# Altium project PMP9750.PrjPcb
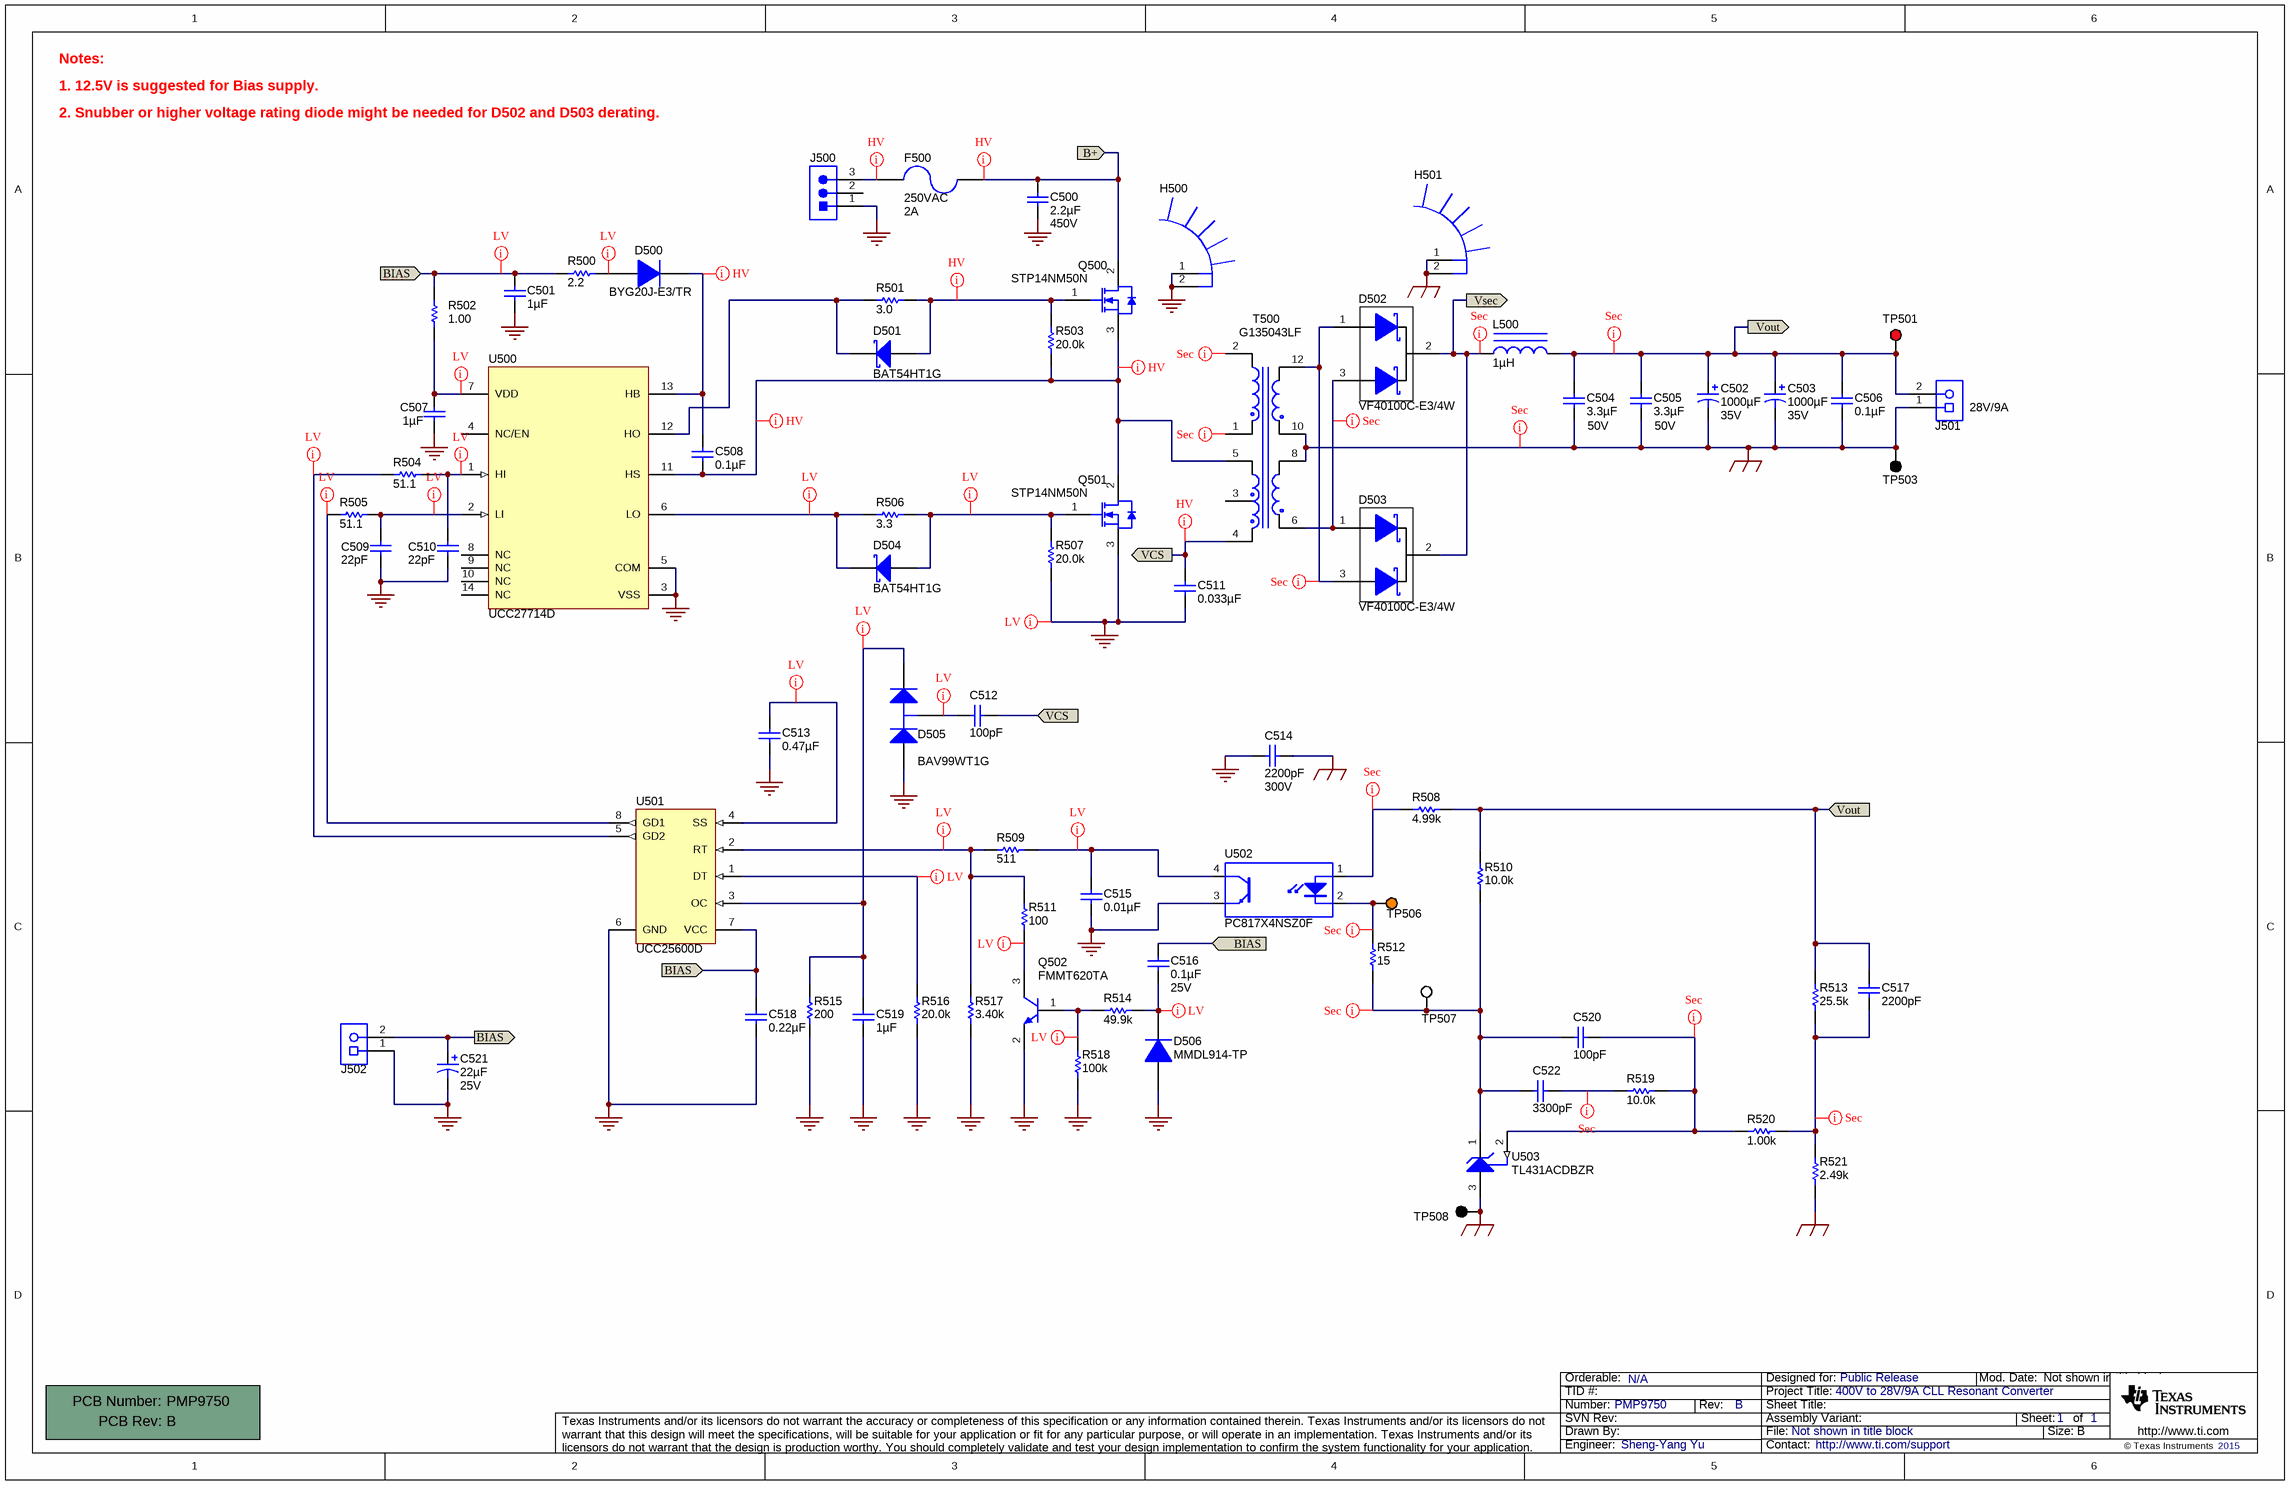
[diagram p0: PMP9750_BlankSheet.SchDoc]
TechSupport: http://www.ti.com/support; SCH_Rev: B; PRJ_Title: 400V to 28V/9A CLL Resonant Converter; PRJ_Number: PMP9750; PRJ_Engineer: Sheng-Yang Yu; PRJ_Customer: Public Release; PCB_Rev: B; PCB_Layout: Sheng-Yang Yu; EVM_Orderable: N/A; CopyrightYear: 2015
1 sheet, 73 parts. Net scope: flat (ports and power ports of the same name join across sheets).
Board file: PMP9750_TID.PcbDoc

## Sheet PMP9750_BlankSheet.SchDoc
size 431 x 279 mm; Date: Not shown in title block; ApprovedBy: Not shown in title block; CheckedBy: Not shown in title block; Author: Not shown in title block; CompanyName: Not shown in title block; Engineer: Not shown in title block; Organization: Not shown in title block; Address1: Not shown in title block; Address2: Not shown in title block; Address3: Not shown in title block; Address4: Not shown in title block; DocumentNumber: 1; Revision: Use project parameter SCH_Rev; SheetNumber: 1; SheetTotal: 1; PageSetup: Record=PageOptions¦CenterHorizontal=True¦CenterVertical=True¦PrintScale=1.00¦XCorrection=1.00¦YCorrection=1.00¦PrintKind=0¦BorderSize=5000000¦LeftOffset=0¦BottomOffset=0¦Orientation=2¦PaperLength=1000¦PaperWidth=1000¦Scale=100¦PaperSource=15¦PrintQuality=600¦MediaType=1¦DitherType=10¦PaperKind=Letter¦PrintScaleMode=1

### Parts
!PCB500  Printed Circuit Board  (value not drawn)  (mechanical)
C500  ValueDisplayed: 2.2µF  Value2: 450V  [MPK_1800x2000x1350]  (hidden comment: 450MPK225J)
C501  ValueDisplayed: 1µF  [0603]  (hidden comment: UMK107AB7105KA-T)
C502  ValueDisplayed: 1000µF  Value2: 35V  [CAPPR5-10X20]  (hidden comment: 35ZLH1000MEFC12.5X20)
C503  ValueDisplayed: 1000µF  Value2: 35V  [CAPPR5-10X20]  (hidden comment: 35ZLH1000MEFC12.5X20)
C504  ValueDisplayed: 3.3µF  Value2: 50V  [1210]  (hidden comment: C3225X7R1H335M)
C505  ValueDisplayed: 3.3µF  Value2: 50V  [1210]  (hidden comment: C3225X7R1H335M)
C506  ValueDisplayed: 0.1µF  [0805_HV]  (hidden comment: 08055C104KAT2A)
C507  ValueDisplayed: 1µF  [0805_HV]  (hidden comment: GMK212B7105KG-T)
C508  ValueDisplayed: 0.1µF  [1206]  (hidden comment: 12065C104KAT2A)
C509  ValueDisplayed: 22pF  [0603]  (hidden comment: C0603C220J5GACTU)
C510  ValueDisplayed: 22pF  [0603]  (hidden comment: C0603C220J5GACTU)
C511  ValueDisplayed: 0.033µF  [CAPRR1500W80L1800T950H1800]  (hidden comment: 121MPE333J)
C512  ValueDisplayed: 100pF  [1808]  (hidden comment: VJ1808Y101KXEAT5Z)
C513  ValueDisplayed: 0.47µF  [0603]  (hidden comment: C0603C474K4RACTU)
C514  ValueDisplayed: 2200pF  Value2: 300V  [E_900x700x900]  (hidden comment: DE6E3KJ222MN3A)
C515  ValueDisplayed: 0.01µF  [0603]  (hidden comment: C0603C103K5RACTU)
C516  ValueDisplayed: 0.1µF  Value2: 25V  [0603]  (hidden comment: 06033C104JAT2A)
C517  ValueDisplayed: 2200pF  [0603]  (hidden comment: C0603C222K5RAC)
C518  ValueDisplayed: 0.22µF  [0805_HV]  (hidden comment: 08053C224JAT2A)
C519  ValueDisplayed: 1µF  [0603]  (hidden comment: C0603C105K4PACTU)
C520  ValueDisplayed: 100pF  [0603]  (hidden comment: C1608C0G1H101J)
C521  ValueDisplayed: 22µF  Value2: 25V  [ML_500x500]  (hidden comment: 25ML22MEFC5X5)
C522  ValueDisplayed: 3300pF  [0603]  (hidden comment: 06031C332KAT2A)
D500  BYG20J-E3/TR  [SMA]
D501  BAT54HT1G  [sod-323]
D502  VF40100C-E3/4W  [TO-220AB]
D503  VF40100C-E3/4W  [TO-220AB]
D504  BAT54HT1G  [sod-323]
D505  BAV99WT1G  [SOT-323]
D506  MMDL914-TP  [sod-323]
F500  VAC_V: 250VAC  Irating_A: 2A  [FUSE_372]  (hidden comment: 37212000001)
H500  578622B03200G  [HSINK_578622B03200G]  (value not drawn)
H501  513002B02500G  [HSINK_513201B02500]  (value not drawn)
J500  1715734  [Phoenix_1715734]  (value not drawn)
J501  1715721  [PhoenixContact_1715721]  (value not drawn)
J502  1715721  [PhoenixContact_1715721]  (value not drawn)
L500  ValueDisplayed: 1µH  [WE-HCC_1210]  (hidden comment: 7443320100)
Q500  STP14NM50N  [TO-220AB_100mil]
Q501  STP14NM50N  [TO-220AB_100mil]
Q502  FMMT620TA  [SOT-23]
R500  ValueDisplayed: 2.2  [0805_HV]  (hidden comment: CRCW08052R20JNEA)
R501  value 3.0  [0603]  (hidden comment: CRCW06033R00JNEA)
R502  value 1.00  [0805_HV]  (hidden comment: ERJ-6RQF1R0V)
R503  value 20.0k  [0805_HV]  (hidden comment: CRCW080520K0FKEA)
R504  ValueDisplayed: 51.1  [0603]  (hidden comment: CRCW060351R1FKEA)
R505  ValueDisplayed: 51.1  [0603]  (hidden comment: CRCW060351R1FKEA)
R506  ValueDisplayed: 3.3  [1206]  (hidden comment: CRCW12063R30JNEA)
R507  value 20.0k  [0805_HV]  (hidden comment: CRCW080520K0FKEA)
R508  value 4.99k  [0805_HV]  (hidden comment: CRCW08054K99FKEA)
R509  ValueDisplayed: 511  [0603]  (hidden comment: CRCW0603511RFKEA)
R510  value 10.0k  [0603]  (hidden comment: CRCW060310K0FKEA)
R511  ValueDisplayed: 100  [0603]  (hidden comment: CRCW0603100RFKEA)
R512  value 15  [0603]  (hidden comment: CRCW060315R0JNEA)
R513  value 25.5k  [0603]  (hidden comment: CRCW060325K5FKEA)
R514  ValueDisplayed: 49.9k  [0603]  (hidden comment: CRCW060349K9FKEA)
R515  value 200  [0603]  (hidden comment: CRCW0603200RFKEA)
R516  value 20.0k  [0603]  (hidden comment: CRCW060320K0FKEA)
R517  value 3.40k  [0603]  (hidden comment: CRCW06033K40FKEA)
R518  ValueDisplayed: 100k  [0603]  (hidden comment: CRCW0603100KFKEA)
R519  value 10.0k  [0603]  (hidden comment: CRCW060310K0FKEA)
R520  value 1.00k  [0603]  (hidden comment: CRCW06031K00FKEA)
R521  value 2.49k  [0603]  (hidden comment: CRCW06032K49FKEA)
T500  G135043LF  [XFMR_GCI-1240x965x1213]
TP501  5000  [Keystone5000]  (value not drawn)
TP503  5001  [Keystone5001]  (value not drawn)
TP506  5003  [Keystone5003]  (value not drawn)
TP507  5002  [Keystone5002]  (value not drawn)
TP508  5001  [Keystone5001]  (value not drawn)
U500  UCC27714D  [D0014A_N]
U501  UCC25600D  [D0008A_N]
U502  PC817X4NSZ0F  [DIP762W60P254L460H350Q4B]
U503  TL431ACDBZR  [DBZ0003A_N]

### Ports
B+ (in), BIAS (in), BIAS (out), VCS (in), VCS (out), Vout (in), Vout (out), Vsec (out)

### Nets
GND: C500.2 C501.1 C507.1 C509.2 C510.2 C511.2 C513.2 C514.2 C515.2 C518.2 C519.2 C521.2(-) D505.1(A) D506.2(A) H500.1 H500.2 J500.1 J502.1 Q501.3(S) Q502.2(E) R507.2 R515.1 R516.1 R517.1 R518.2 U500.3(VSS) U500.5(COM) U501.6(GND) U502.3(E)
GND2: C502.2(-) C503.2(-) C504.2 C505.2 C506.2 C514.1 H501.1 H501.2 J501.1 R521.1 T500.8 T500.10 TP503.1 TP508.1 U503.3(ANODE)
B+: C500.1 F500.1 Q500.2(D) ; port B+
BIAS: C501.2 C516.1 C518.1 C521.1(+) J502.2 R500.1 R502.2 U501.7(VCC) ; port BIAS
VCS: C511.1 C512.1 T500.4 ; port VCS
Vout: C502.1(+) C503.1(+) C504.1 C505.1 C506.1 C517.1 J501.2 L500.2 R508.2 R510.2 R513.2 TP501.1 ; port Vout
Vsec: D502.2(K) D503.2(K) L500.1 ; port Vsec
NetC507_2: C507.2 R502.1 U500.7(VDD)
NetC508_1: C508.1 D500.1(K) U500.13(HB)
NetC508_2: C508.2 Q500.3(S) Q501.2(D) R503.2 T500.5 U500.11(HS)
NetC509_1: C509.1 R505.2 U500.2(LI)
NetC510_1: C510.1 R504.2 U500.1(HI)
NetC512_2: C512.2 D505.3(C)
NetC513_1: C513.1 U501.4(SS)
NetC515_1: C515.1 R509.2 U502.4(C)
NetC516_2: C516.2 D506.1(K) R514.1
NetC517_2: C517.2 R513.1 R520.2 R521.2
NetC519_1: C519.1 D505.2(K) R515.2 U501.3(OC)
NetC520_1: C520.1 R519.2 R520.1 U503.2(REF)
NetC520_2: C520.2 C522.2 R510.1 R512.2 TP507.1 U503.1(CATHODE)
NetC522_1: C522.1 R519.1
NetD500_2: D500.2(A) R500.2
NetD501_1: D501.1(K) R501.1 U500.12(HO)
NetD501_2: D501.2(A) Q500.1(G) R501.2 R503.1
NetD502_1: D502.1(A) D503.3(A) T500.12
NetD502_3: D502.3(A) D503.1(A) T500.6
NetD504_1: D504.1(K) R506.1 U500.6(LO)
NetD504_2: D504.2(A) Q501.1(G) R506.2 R507.1
NetF500_2: F500.2 J500.3
NetQ502_1: Q502.1(B) R514.2 R518.1
NetQ502_3: Q502.3(C) R511.1
NetR504_1: R504.1 U501.5(GD2)
NetR505_1: R505.1 U501.8(GD1)
NetR508_1: R508.1 U502.1(A)
NetR509_1: R509.1 R511.2 R517.2 U501.2(RT)
NetR512_1: R512.1 TP506.1 U502.2(K)
NetR516_2: R516.2 U501.1(DT)

Not connected (* = marked no-connect by the designer): J500 2; T500 1 2 3; U500 4(NC/EN) 8(NC) 9(NC) 10(NC) 14(NC)

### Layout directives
net class HV_pri: B+, NetC508_1, NetC508_2, NetD501_2, NetF500_2, VCS
net class Sec: GND2, NetC517_2, NetC520_1, NetC520_2, NetC522_1, NetD502_1, NetD502_3, NetR508_1, NetR512_1, NetT500_1, NetT500_2, Vout, Vsec
net class LV_pri: BIAS, GND, NetC507_2, NetC509_1, NetC510_1, NetC512_2, NetC513_1, NetC515_1, NetC516_2, NetC519_1, NetD500_2, NetD504_1, NetD504_2, NetQ502_1, NetQ502_3, NetR504_1, NetR505_1, NetR509_1, NetR516_2

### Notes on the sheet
- Notes:
- 1. 12.5V is suggested for Bias supply.
- 2. Snubber or higher voltage rating diode might be needed for D502 and D503 derating.
- (near J501) 28V/9A

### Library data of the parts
!PCB500 = PCB: Manufacturer: Any; PartNumber: PMP9750; SymbolCreator: a0412235
C500 = 450MPK225J: CAP, Film, 2.2 µF, 450 V, +/- 5%, TH; Manufacturer: Rubycon; Polarized: N; CompType: Capacitor; Value: 2.2uF; U/M: EA; Cap_F: 0.0000022; Tolerance_%: 5; Value1: Unknown; VDC_V: 450; TaMin_C: -40; TaMax_C: 105
C501 = UMK107AB7105KA-T: CAP, CERM, 1 µF, 50 V, +/- 10%, X7R, 0603; Manufacturer: Taiyo Yuden; Polarized: N; CompType: Capacitor; Value: 1uF; U/M: EA; Cap_F: 0.000001; Tolerance_%: 10; Value1: Unknown; VDC_V: 50; Value2: 50V; TaMin_C: -55; TaMax_C: 125
C502 C503 = EEU-FR1V681: CAP, AL, 680uF, 35V, +/-20%, TH; Manufacturer: Rubycon; Polarized: Y; CompType: Capacitor; Value: 1000uF; U/M: EA; Tolerance_%: 20; Value1: Unknown; VDC_V: 35; IRMS_A: 2.47; TaMin_C: -40; TaMax_C: 105
C504 C505 = C3225X7R1H335M: CAP, CERM, 3.3uF, 50V, +/-20%, X7R, 1210; Manufacturer: TDK; Polarized: N; CompType: Capacitor; U/M: EA; Cap_F: 0.0000033; Tolerance_%: 20; Value1: Unknown; VDC_V: 50; TaMin_C: -55; TaMax_C: 125
C506 = 08055C104KAT2A: CAP, CERM, 0.1uF, 50V, +/-10%, X7R, 0805; Manufacturer: AVX; Polarized: N; CompType: Capacitor; U/M: EA; Cap_F: 0.0000001; Tolerance_%: 10; ESR_Ohm: 0.024; Value1: 0.024 ohm; VDC_V: 50; TaMin_C: -55; TaMax_C: 125; Cap_Case: 0805
C507 = GMK212B7105KG-T: CAP, CERM, 1uF, 35V, +/-10%, X7R, 0805; Manufacturer: Taiyo Yuden; Polarized: N; CompType: Capacitor; U/M: EA; Cap_F: 0.000001; Tolerance_%: 10; Value1: Unknown; VDC_V: 35; TaMin_C: -55; TaMax_C: 125; Cap_Case: 0805
C508 = 12065C104KAT2A: CAP, CERM, 0.1 µF, 50 V, +/- 10%, X7R, 1206; Manufacturer: AVX; Polarized: N; CompType: Capacitor; Value: 0.1uF; U/M: EA; Cap_F: 0.0000001; Tolerance_%: 10; ESR_ohm: 0.037; Value1: 0.037 ohm; VDC_V: 50; Value2: 50V; TaMin_C: -55; TaMax_C: 125
C509 C510 = C0603C220J5GACTU: CAP, CERM, 22 pF, 50 V, +/- 5%, C0G/NP0, 0603; Manufacturer: Kemet; Polarized: N; CompType: Capacitor; Value: 22pF; U/M: EA; Cap_F: 0.000000000022; Tolerance_%: 5; Value1: Unknown; VDC_V: 50; Value2: 50V; TaMin_C: -55; TaMax_C: 125
C511 = 121MPE333J: CAP, Film, 0.033uF, 1250V, +/-5%, TH; Manufacturer: Rubycon; Polarized: N; CompType: Capacitor; U/M: EA; Cap_F: 0.000000033; Tolerance_%: 5; Value1: Unknown; VDC_V: 1250; TaMin_C: -40; TaMax_C: 105; Cap_Case: 18x9.5x18mm
C512 = VJ1808Y101KXEAT5Z: CAP, CERM, 100pF, 500V, +/-10%, X7R, 1808; Manufacturer: Vishay-Vitramon; Polarized: N; CompType: Capacitor; U/M: EA; Cap_F: 0.0000000001; Tolerance_%: 10; Value1: Unknown; VDC_V: 500; TaMin_C: -55; TaMax_C: 125
C513 = C0603C474K4RACTU: CAP, CERM, 0.47uF, 16V, +/-10%, X7R, 0603; Manufacturer: Kemet; Polarized: N; CompType: Capacitor; U/M: EA; Cap_F: 0.00000047; Tolerance_%: 10; Value1: Unknown; VDC_V: 16; TaMin_C: -55; TaMax_C: 125
C514 = DE6E3KJ222MN3A: CAP, CERM, 2200 pF, 300 V, +/- 20%, E, TH, 2- Leads, Body 9x7mm, Pin Spacing 7.5mm; Manufacturer: MuRata; Polarized: N; CompType: Capacitor; Value: 2200pF; U/M: EA; Cap_F: 0.0000000022; Tolerance_%: 20; Value1: Unknown; VDC_V: 300; TaMin_C: -40; TaMax_C: 125; Cap_Case: 9x7x9mm
C515 = C0603C103K5RACTU: CAP, CERM, 0.01uF, 50V, +/-10%, X7R, 0603; Manufacturer: Kemet; Polarized: N; CompType: Capacitor; U/M: EA; Cap_F: 0.00000001; Tolerance_%: 10; Value1: Unknown; VDC_V: 50; TaMin_C: -55; TaMax_C: 125
C516 = 06033C104JAT2A: CAP, CERM, 0.1 µF, 25 V, +/- 5%, X7R, 0603; Manufacturer: AVX; Polarized: N; CompType: Capacitor; Value: 0.1uF; U/M: EA; Cap_F: 0.0000001; Tolerance_%: 5; ESR_ohm: 0.05; Value1: 0.05 ohm; VDC_V: 25; TaMin_C: -55; TaMax_C: 125
C517 = C0603C222K5RAC: CAP, CERM, 2200pF, 50V, +/-10%, X7R, 0603; Manufacturer: Kemet; Polarized: N; CompType: Capacitor; U/M: EA; Cap_F: 0.0000000022; Tolerance_%: 10; Value1: Unknown; VDC_V: 50; TaMin_C: -55; TaMax_C: 125
C518 = 08053C224JAT2A: CAP, CERM, 0.22uF, 25V, +/-5%, X7R, 0805; Manufacturer: AVX; Polarized: N; CompType: Capacitor; U/M: EA; Cap_F: 0.00000022; Tolerance_%: 5; ESR_Ohm: 0.016; Value1: 0.016 ohm; VDC_V: 25; TaMin_C: -55; TaMax_C: 125; Cap_Case: 0805
C519 = C0603C105K4PACTU: CAP, CERM, 1uF, 16V, +/-10%, X5R, 0603; Manufacturer: Kemet; Polarized: N; CompType: Capacitor; U/M: EA; Cap_F: 0.000001; Tolerance_%: 10; Value1: Unknown; VDC_V: 16; TaMin_C: -55; TaMax_C: 85
C520 = C1608C0G1H101J: CAP, CERM, 100pF, 50V, +/-5%, C0G/NP0, 0603; Manufacturer: TDK; Polarized: N; CompType: Capacitor; U/M: EA; Cap_F: 0.0000000001; Tolerance_%: 5; ESR_Ohm: 0.1679; Value1: 0.1679 ohm; VDC_V: 50; TaMin_C: -55; TaMax_C: 125
C521 = 25ML22MEFC5X5: CAP, AL, 22 µF, 25 V, +/- 20%, TH; Manufacturer: Rubycon; Polarized: Y; CompType: Capacitor; Value: 22uF; U/M: EA; Cap_F: 0.000022; Tolerance_%: 20; Value1: Unknown; VDC_V: 25; IRMS_A: 0.042; TaMin_C: -40; TaMax_C: 105; Cap_Case: 5x5
C522 = 06031C332KAT2A: CAP, CERM, 3300pF, 100V, +/-10%, X7R, 0603; Manufacturer: AVX; Polarized: N; CompType: Capacitor; U/M: EA; Cap_F: 0.0000000033; Tolerance_%: 10; ESR_Ohm: 0.159; Value1: 0.159 ohm; VDC_V: 100; TaMin_C: -55; TaMax_C: 125
D500 = BYG20J-E3/TR: Diode, Ultrafast, 600V, 1.5A, SMA; Manufacturer: Vishay-Semiconductor; U/M: EA; Vf_V: 1.4; Value2: 1.4V; Io_A: 1.5; Vr_V: 600; TJmax_C: 150
D501 D504 = BAT54HT1G: Diode, Schottky, 30V, 0.2A, SOD-323; Manufacturer: ON Semiconductor; Value: 0.35V; U/M: EA; Vf_V: 0.35; Io_A: 0.2; Vr_V: 30
D502 D503 = VF40100C-E3/4W: Diode, Schottky, 100 V, 20 A, TH; Manufacturer: Vishay-Semiconductor; SymbolCreator: a0411947; U/M: EA; Vf_V: 0.73; Value: 100V; Value1: 20A; Value2: 0.73V; Io_A: 20; Vr_V: 100; TJmax_C: 150; RJC_CperW: 2
D505 = BAV99WT1G: Diode, P-N, 70V, 0.2A, SOT-323; Manufacturer: Fairchild Semiconductor; Value: 0.63V; U/M: EA; Vf_V: 0.63; Io_A: 0.2; Vr_V: 70; TJmax_C: 150
D506 = MMDL914-TP: Diode, Switching, 100 V, 0.2 A, SOD-323; Manufacturer: Micro Commercial Components; U/M: EA; Vf_V: 1; Value: 100V; Value1: 0.2A; Value2: 1V; Io_A: 0.2; Vr_V: 100; TJmax_C: 150; RJC_CperW: 635
F500 = 37212000001: Fuse, 2 A, 250 V, TH; Manufacturer: Littelfuse; U/M: EA; OpeningTime_200%_max: 2; VDC_V: 250; Vdrop: 0.085; Soldering_Wave_MaxTemp_C: 260; Soldering_Wave_MaxTime_s: 5
H500 = 578622B03200G: Twin Channel Style Heat Sink, TO-220, Vertical; Manufacturer: Aavid; SymbolCreator: a0799628
H501 = 513201B02500G: BOARD LEVEL HEATSINK .5" TO-220; Manufacturer: Aavid; SymbolCreator: a0799628
J500 = 1715734: TERM BLOCK 3POS 5.08MM, TH; Manufacturer: Phoenix Contact; SymbolCreator: a0799628; CompType: Header; U/M: EA
J501 J502 = 1715721: Conn Term Block, 2POS, 5.08mm, TH; Manufacturer: Phoenix Contact; SymbolCreator: a0412235; CompType: Terminal Block; U/M: EA; Value: 2x1
L500 = 7443320100: Inductor, Shielded Drum Core, Ferrite, 1 µH, 24 A, 0.0012 ohm, SMD; Manufacturer: Wurth Elektronik; Value: 1uH; Ind_H: 1.0E-6; Imax_A: 24; Irms: 24A @ 50C rise; Isat: 32A @ 30% inductance drop; DCR_ohm: 0.0012; Value2: 24A
Q500 Q501 = SPP06N80C3: MOSFET N-CH 500V 12A TO-220; Manufacturer: ST; Alternate Manufacturer: None; U/M: EA; ChType: N; IdsMax_A: 6
Q502 = MMBT2222A, Fairchild Semiconductor: TRANS NPN 80V 1.5A SOT23-3; Manufacturer: Diodes; CompType: BJT; PNP: 0; NPN: 1; Vcesat1_V: 0.3; IcRated_A: 0.15; Value1: 0.15 A; HfeMax: 300; TaMin_C: -55; TaMax_C: 150; U/M: EA
R500 = CRCW08052R20JNEA: RES, 2.2, 5%, 0.125 W, 0805; Manufacturer: Vishay-Dale; CompType: Resistor; Value: 2.2; Value_Code: 2R20; Tolerance_%: 5; Power_W: 0.125; Value2: 0.125W; VDC_V: 150; TempCo: 200 ppm/C; EIA_Code: E24; U/M: EA
R501 = CRCW06033R00JNEA: RES, 3.0 ohm, 5%, 0.1W, 0603; Manufacturer: Vishay-Dale; CompType: Resistor; Res_ohm: 3; Value_Code: 3R00; Tolerance_%: 5; Power_W: 0.1; VDC_V: 75; TempCo: 200 ppm/C; EIA_Code: E24; U/M: EA
R502 = ERJ-6RQF1R0V: RES, 1.00 ohm, 1%, 0.125W, 0805; Manufacturer: Panasonic; CompType: Resistor; Res_ohm: 1; Value_Code: 1R00; Power_W: 0.125; TempCo: 200 ppm/C; EIA_Code: E96; U/M: EA
R503 R507 = CRCW080520K0FKEA: RES, 20.0k ohm, 1%, 0.125W, 0805; Manufacturer: Vishay-Dale; CompType: Resistor; Res_ohm: 20000; Value_Code: 20k0; Tolerance_%: 1; Power_W: 0.125; VDC_V: 150; TempCo: 100 ppm/C; EIA_Code: E96; U/M: EA
R504 R505 = CRCW060351R1FKEA: RES, 51.1, 1%, 0.1 W, 0603; Manufacturer: Vishay-Dale; CompType: Resistor; Value: 51.1; Value_Code: 51R1; Tolerance_%: 1; Power_W: 0.1; Value2: 0.1W; VDC_V: 75; TempCo: 100 ppm/C; EIA_Code: E96; U/M: EA
R506 = CRCW12063R30JNEA: RES, 3.3, 5%, 0.25 W, 1206; Manufacturer: Vishay-Dale; CompType: Resistor; Value: 3.3; Value_Code: 3R30; Tolerance_%: 5; Power_W: 0.25; Value2: 0.25W; VDC_V: 200; TempCo: 200 ppm/C; EIA_Code: E24; U/M: EA
R508 = CRCW08054K99FKEA: RES, 4.99k ohm, 1%, 0.125W, 0805; Manufacturer: Vishay-Dale; CompType: Resistor; Res_ohm: 4990; Value_Code: 4k99; Tolerance_%: 1; Power_W: 0.125; VDC_V: 150; TempCo: 100 ppm/C; EIA_Code: E96; U/M: EA
R509 = CRCW0603511RFKEA: RES, 511, 1%, 0.1 W, 0603; Manufacturer: Vishay-Dale; CompType: Resistor; Value: 511; Value_Code: 511R; Tolerance_%: 1; Power_W: 0.1; Value2: 0.1W; VDC_V: 75; TempCo: 100 ppm/C; EIA_Code: E96; U/M: EA
R510 R519 = CRCW060310K0FKEA: RES, 10.0k ohm, 1%, 0.1W, 0603; Manufacturer: Vishay-Dale; CompType: Resistor; Res_ohm: 10000; Value_Code: 10k0; Tolerance_%: 1; Power_W: 0.1; VDC_V: 75; TempCo: 100 ppm/C; EIA_Code: E96; U/M: EA
R511 = CRCW0603100RFKEA: RES, 100, 1%, 0.1 W, 0603; Manufacturer: Vishay-Dale; CompType: Resistor; Value: 100; Value_Code: 100R; Tolerance_%: 1; Power_W: 0.1; Value2: 0.1W; VDC_V: 75; TempCo: 100 ppm/C; EIA_Code: E96; U/M: EA
R512 = CRCW060315R0JNEA: RES, 15 ohm, 5%, 0.1W, 0603; Manufacturer: Vishay-Dale; CompType: Resistor; Value_Code: 15R0; Tolerance_%: 5; Power_W: 0.1; VDC_V: 75; TempCo: 200 ppm/C; EIA_Code: E24; U/M: EA
R513 = CRCW060325K5FKEA: RES, 25.5k ohm, 1%, 0.1W, 0603; Manufacturer: Vishay-Dale; CompType: Resistor; Res_ohm: 25500; Value_Code: 25k5; Tolerance_%: 1; Power_W: 0.1; VDC_V: 75; TempCo: 100 ppm/C; EIA_Code: E96; U/M: EA
R514 = CRCW060349K9FKEA: RES, 49.9 k, 1%, 0.1 W, 0603; Manufacturer: Vishay-Dale; CompType: Resistor; Value: 49.9k; Res_ohm: 49900; Value_Code: 49k9; Tolerance_%: 1; Power_W: 0.1; Value2: 0.1W; VDC_V: 75; TempCo: 100 ppm/C; EIA_Code: E96; U/M: EA
R515 = CRCW0603200RFKEA: RES, 200 ohm, 1%, 0.1W, 0603; Manufacturer: Vishay-Dale; CompType: Resistor; Value_Code: 200R; Tolerance_%: 1; Power_W: 0.1; VDC_V: 75; TempCo: 100 ppm/C; EIA_Code: E96; U/M: EA
R516 = CRCW060320K0FKEA: RES, 20.0k ohm, 1%, 0.1W, 0603; Manufacturer: Vishay-Dale; CompType: Resistor; Res_ohm: 20000; Value_Code: 20k0; Tolerance_%: 1; Power_W: 0.1; VDC_V: 75; TempCo: 100 ppm/C; EIA_Code: E96; U/M: EA
R517 = CRCW06033K40FKEA: RES, 3.40k ohm, 1%, 0.1W, 0603; Manufacturer: Vishay-Dale; CompType: Resistor; Res_ohm: 3400; Value_Code: 3k40; Tolerance_%: 1; Power_W: 0.1; VDC_V: 75; TempCo: 100 ppm/C; EIA_Code: E96; U/M: EA
R518 = CRCW0603100KFKEA: RES, 100 k, 1%, 0.1 W, 0603; Manufacturer: Vishay-Dale; CompType: Resistor; Value: 100k; Res_ohm: 100000; Tolerance_%: 1; Power_W: 0.1; Value2: 0.1W; VDC_V: 75; TempCo: 100 ppm/C; EIA_Code: E96; U/M: EA
R520 = CRCW06031K00FKEA: RES, 1.00k ohm, 1%, 0.1W, 0603; Manufacturer: Vishay-Dale; CompType: Resistor; Res_ohm: 1000; Value_Code: 1k00; Tolerance_%: 1; Power_W: 0.1; VDC_V: 75; TempCo: 100 ppm/C; EIA_Code: E96; U/M: EA
R521 = CRCW06032K49FKEA: RES, 2.49k ohm, 1%, 0.1W, 0603; Manufacturer: Vishay-Dale; CompType: Resistor; Res_ohm: 2490; Value_Code: 2k49; Tolerance_%: 1; Power_W: 0.1; VDC_V: 75; TempCo: 100 ppm/C; EIA_Code: E96; U/M: EA
T500 = G135043LF: Transformer, 360uH, TH; Manufacturer: GCI Technologies; SymbolCreator: a0411947; DCR_Ohm: 0.26; U/M: EA
TP501 = 5000: Test Point, Miniature, Red, TH; Manufacturer: Keystone; CompType: Test Point Loop; U/M: EA
TP503 TP508 = 5001: Test Point, Miniature, Black, TH; Manufacturer: Keystone; CompType: Test Point Loop; U/M: EA
TP506 = 5003: Test Point, Miniature, Orange, TH; Manufacturer: Keystone; CompType: Test Point Loop; U/M: EA
TP507 = 5002: Test Point, Miniature, White, TH; Manufacturer: Keystone; CompType: Test Point Loop; U/M: EA
U500 = UCC27714D: High-Speed,4A, 600V High-side Low-side Gate Driver Device, D0014A; Manufacturer: Texas Instruments; SymbolCreator: a0411947; CompType: IC; U/M: EA
U501 = UCC25600D: High-Performance Resonant Mode Controller with Voltage Control, 50 % Duty Cycle, -40 to +125 degC, 8-pin SOIC (D), Green (RoHS & no Sb/Br); Manufacturer: Texas Instruments; Alternate Manufacturer: None; Alternate PartNumber: Equivalent; Duty Cycle(Max)(%): 50; Frequency(Max)(kHz): 350; Rating: Catalog; Regulated Outputs(#): 2; SubFamily: PWM Controller; Topology: Resonant, Half-Bridge; UVLO Thresholds On/Off(V): 10.5/9.5
U502 = LTV-817: Opto-Isolator, 1 Channel, TH; CompType: OPTOCOUPLER; U/M: EA
U503 = TL431ACDBZR: Adjustable Precision Shunt Regulator, 34 ppm / degC, 100 mA, 0 to 70 degC, 3-pin SOT-23 (DBZ), Green (RoHS & no Sb/Br); Manufacturer: Texas Instruments; Alternate Manufacturer: None; Alternate PartNumber: Equivalent; Initial Accuracy @ 25/deg C(%): 1; Iout/Iz(Max)(mA): 100; Min Iz for Regulation(uA): 600; Rating: Catalog; SubFamily: Shunt Voltage Reference; Temp Coeff(Typ)(ppm/ degree C): 34; VO Adj(Max)(V): 36; VO Adj(Min)(V): 2.495

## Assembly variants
001: not fitted FID1 FID2 FID3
